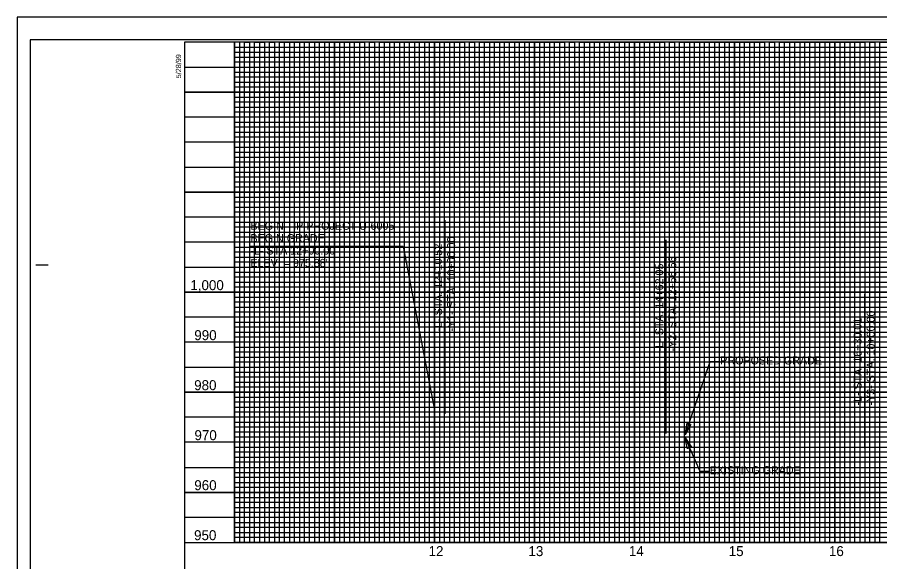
# Model space of a CAD drawing. Extents: x 1623313 to 1628771, y 891211 to 901910.
# Drawn here: x 1623313 to 1624175, y 901315 to 901859 of the extents above; entities that cross this region are included whole.
import ezdxf

# ---------------------------------------------------------------- set-up
doc = ezdxf.new("R2010")
doc.units = 0
for name, color, linetype in [('Default', 7, 'Continuous'), ('Prop DSN Text', 7, 'Continuous'), ('Prop VPI Label', 7, 'Continuous'), ('Scratch_Level_0', 7, 'Continuous'), ('Sheet Cutting Line CELL', 7, 'Continuous'), ('Sheet DOT Grid CELL', 7, 'Continuous'), ('Sheet Layout Profile Border Port 1', 7, 'Continuous'), ('Sheet Plot Border Inside CELL', 7, 'Continuous'), ('Sheet Plot Border Outside CELL', 7, 'Continuous'), ('Sheet Profile CELL', 7, 'Continuous'), ('Sheet Profile Grid Major CELL', 7, 'Continuous'), ('Sheet Profile Grid Middle CELL', 7, 'Continuous'), ('Sheet Profile Grid Minor CELL', 7, 'Continuous'), ('Typical Terminator CELL', 7, 'Continuous')]:
    doc.layers.add(name, color=color, linetype=linetype)

msp = doc.modelspace()

# ---------------------------------------------------------------- linework, layer by layer
at = {"layer": 'Prop DSN Text'}
for points in [[(1623740.48, 901480.56), (1623740.66, 901656.7)], [(1623961.49, 901443.17), (1623961.68, 901636.82)], [(1624160.08, 901428.57), (1624160.08, 901428.57), (1624160.15, 901582.49)], [(1623980.61, 901441.91), (1624005.61, 901515.32), (1624015.61, 901515.32)], [(1623740.47, 901463.06), (1623740.48, 901480.56)], [(1623980.04, 901439.52), (1623995.04, 901405.59), (1624005.04, 901405.59)]]:
    msp.add_lwpolyline(points, dxfattribs=at)
at = {"layer": 'Prop VPI Label'}
msp.add_line((1623698.63, 901630.21), (1623729.95, 901466.57), dxfattribs=at)
msp.add_lwpolyline([(1623698.63, 901630.21), (1623545.98, 901630.21), (1623698.63, 901630.21)], dxfattribs=at)
at = {"layer": 'Scratch_Level_0'}
msp.add_lwpolyline([(1623529.95, 901824.45), (1624929.95, 901824.45), (1624929.95, 901334.45), (1623529.95, 901334.45)], close=True, dxfattribs=at)
at = {"layer": 'Sheet Cutting Line CELL'}
for p, q in [((1624996.95, 901859.45), (1623312.95, 901859.45)), ((1623312.95, 901859.45), (1623312.95, 900759.45))]:
    msp.add_line(p, q, dxfattribs=at)
at = {"layer": 'Sheet DOT Grid CELL'}
for p, q in [((1623529.95, 901334.45), (1623529.95, 901834.45)), ((1623579.95, 901334.45), (1623579.95, 901834.45)), ((1623629.95, 901334.45), (1623629.95, 901834.45)), ((1623679.95, 901334.45), (1623679.95, 901834.45)), ((1623729.95, 901334.45), (1623729.95, 901834.45)), ((1623779.95, 901334.45), (1623779.95, 901834.45)), ((1623829.95, 901334.45), (1623829.95, 901834.45)), ((1623879.95, 901334.45), (1623879.95, 901834.45)), ((1623929.95, 901334.45), (1623929.95, 901834.45)), ((1623979.95, 901334.45), (1623979.95, 901834.45)), ((1624029.95, 901334.45), (1624029.95, 901834.45)), ((1624079.95, 901334.45), (1624079.95, 901834.45)), ((1624129.95, 901334.45), (1624129.95, 901834.45)), ((1624779.9, 901784.45), (1623479.95, 901784.45)), ((1624779.9, 901734.45), (1623479.95, 901734.45)), ((1624779.95, 901684.45), (1623479.95, 901684.45)), ((1624979.95, 901634.45), (1623479.95, 901634.45)), ((1624979.95, 901584.45), (1623479.95, 901584.45)), ((1624979.95, 901534.45), (1623479.95, 901534.45)), ((1624979.95, 901484.45), (1623479.95, 901484.45)), ((1624979.95, 901434.45), (1623479.95, 901434.45)), ((1624979.95, 901384.45), (1623479.95, 901384.45))]:
    msp.add_line(p, q, dxfattribs=at)
at = {"layer": 'Sheet Layout Profile Border Port 1'}
msp.add_lwpolyline([(1623529.95, 901673.4), (1623529.95, 901334.45), (1624929.95, 901334.45), (1624929.95, 901673.4)], dxfattribs=at)
at = {"layer": 'Sheet Plot Border Inside CELL'}
msp.add_lwpolyline([(1623325.95, 900781.9), (1624992.45, 900781.9), (1624992.45, 901837), (1623325.95, 901837)], close=True, dxfattribs=at)
at = {"layer": 'Sheet Plot Border Outside CELL'}
msp.add_lwpolyline([(1623312.95, 900759.45), (1624996.95, 900759.45), (1624996.95, 901859.45), (1623312.95, 901859.45)], close=True, dxfattribs=at)
at = {"layer": 'Sheet Profile CELL'}
for p, q in [((1623331.45, 901611.95), (1623343.95, 901611.95)), ((1623479.95, 901334.45), (1624979.95, 901334.45))]:
    msp.add_line(p, q, dxfattribs=at)
msp.add_lwpolyline([(1624979.95, 901834.45), (1623479.95, 901834.45), (1623479.95, 900784.45), (1624979.95, 900784.45)], close=True, dxfattribs=at)
at = {"layer": 'Sheet Profile Grid Major CELL'}
for points in [[(1623529.95, 901834.45), (1623529.95, 901334.45), (1623579.95, 901334.45), (1623579.95, 901834.45), (1623629.95, 901834.45), (1623629.95, 901334.45), (1623679.95, 901334.45), (1623679.95, 901834.45), (1623729.95, 901834.45), (1623729.95, 901334.45), (1623779.95, 901334.45), (1623779.95, 901834.45), (1623829.95, 901834.45), (1623829.95, 901334.45), (1623879.95, 901334.45), (1623879.95, 901834.45), (1623929.95, 901834.45), (1623929.95, 901334.45), (1623979.95, 901334.45), (1623979.95, 901834.45), (1624029.95, 901834.45), (1624029.95, 901334.45), (1624079.95, 901334.45), (1624079.95, 901834.45), (1624129.95, 901834.45), (1624129.95, 901334.45), (1624179.95, 901334.45)], [(1623479.95, 901784.45), (1624779.95, 901784.45)], [(1624779.95, 901734.45), (1623479.95, 901734.45), (1623479.95, 901684.45), (1624779.95, 901684.45)], [(1624979.95, 901634.45), (1623479.95, 901634.45), (1623479.95, 901584.45), (1624979.95, 901584.45)], [(1624979.95, 901534.45), (1623479.95, 901534.45), (1623479.95, 901484.45), (1624979.95, 901484.45)], [(1624979.95, 901434.45), (1623479.95, 901434.45), (1623479.95, 901434.45), (1623479.95, 901384.45), (1624979.95, 901384.45)]]:
    msp.add_lwpolyline(points, dxfattribs=at)
at = {"layer": 'Sheet Profile Grid Middle CELL'}
msp.add_line((1623479.95, 901809.45), (1624779.9, 901809.45), dxfattribs=at)
for points in [[(1623554.95, 901834.45), (1623554.95, 901334.45), (1623604.95, 901334.45), (1623604.95, 901834.45), (1623654.95, 901834.45), (1623654.95, 901334.45), (1623704.95, 901334.45), (1623704.95, 901834.45), (1623754.95, 901834.45), (1623754.95, 901334.45), (1623804.95, 901334.45), (1623804.95, 901834.45), (1623854.95, 901834.45), (1623854.95, 901334.45), (1623904.95, 901334.45), (1623904.95, 901834.45), (1623954.95, 901834.45), (1623954.95, 901334.45), (1624004.95, 901334.45), (1624004.95, 901834.45), (1624054.95, 901834.45), (1624054.95, 901334.45), (1624104.95, 901334.45), (1624104.95, 901334.45), (1624104.95, 901834.45), (1624154.95, 901834.45), (1624154.95, 901334.45), (1624204.95, 901334.45)], [(1624779.95, 901759.45), (1623479.95, 901759.45), (1623479.95, 901709.45), (1624779.95, 901709.45)], [(1624979.95, 901659.45), (1623479.95, 901659.45), (1623479.95, 901609.45), (1624804.95, 901609.45)], [(1624979.95, 901559.45), (1623479.95, 901559.45), (1623479.95, 901509.45), (1624979.95, 901509.45)], [(1624979.95, 901459.45), (1623479.95, 901459.45), (1623479.95, 901409.45), (1624979.95, 901409.45)], [(1624979.95, 901359.45), (1623479.95, 901359.45)]]:
    msp.add_lwpolyline(points, dxfattribs=at)
at = {"layer": 'Sheet Profile Grid Minor CELL'}
for p, q in [((1623529.95, 901829.45), (1624779.95, 901829.45)), ((1623529.95, 901824.45), (1623529.95, 901824.45)), ((1624779.95, 901824.45), (1623529.95, 901824.1)), ((1623529.95, 901819.45), (1624779.95, 901819.45)), ((1624779.9, 901699.45), (1623529.95, 901699.45)), ((1624779.95, 901694.45), (1623529.95, 901694.45)), ((1624779.95, 901689.45), (1623529.95, 901689.45)), ((1623529.95, 901679.45), (1624779.95, 901679.45)), ((1624779.95, 901674.45), (1623529.95, 901674.45)), ((1623529.95, 901669.45), (1624929.95, 901669.45)), ((1624929.95, 901649.45), (1623529.95, 901649.45)), ((1623529.95, 901644.45), (1624929.95, 901644.45)), ((1624929.95, 901624.45), (1623529.95, 901624.45)), ((1623529.95, 901619.45), (1624929.95, 901619.45)), ((1624929.95, 901599.45), (1623529.95, 901599.45)), ((1623529.95, 901594.45), (1624929.95, 901594.45)), ((1624929.95, 901589.45), (1623529.95, 901589.45)), ((1623529.95, 901579.45), (1624929.95, 901579.45)), ((1624929.95, 901574.45), (1623529.95, 901574.45)), ((1623529.95, 901569.45), (1624929.95, 901569.45)), ((1624929.95, 901564.45), (1623529.95, 901564.45)), ((1623529.95, 901554.45), (1624929.95, 901554.45)), ((1624929.95, 901549.45), (1623529.95, 901549.45)), ((1623529.95, 901544.45), (1624929.95, 901544.45)), ((1624929.95, 901539.45), (1623529.95, 901539.45)), ((1623529.95, 901529.45), (1624929.95, 901529.45)), ((1624929.95, 901524.45), (1623529.95, 901524.45)), ((1623529.95, 901519.45), (1624929.95, 901519.45)), ((1624929.95, 901514.45), (1623529.95, 901514.45)), ((1623529.95, 901504.45), (1624929.95, 901504.45)), ((1624929.95, 901499.45), (1623529.95, 901499.45)), ((1623529.95, 901494.45), (1624929.95, 901494.45)), ((1624929.95, 901489.45), (1623529.95, 901489.45)), ((1623529.95, 901479.45), (1624929.95, 901479.45)), ((1624929.95, 901474.45), (1623529.95, 901474.45)), ((1623529.95, 901469.45), (1624929.95, 901469.45)), ((1624929.95, 901464.45), (1623529.95, 901464.45)), ((1623529.95, 901454.45), (1624929.95, 901454.45)), ((1624929.95, 901449.45), (1623529.95, 901449.45)), ((1624929.95, 901444.45), (1623529.95, 901444.45)), ((1624929.95, 901439.45), (1623529.95, 901439.45)), ((1623529.95, 901429.45), (1624929.95, 901429.45)), ((1624929.95, 901424.45), (1623529.95, 901424.45)), ((1623529.95, 901419.45), (1624929.95, 901419.45)), ((1624929.95, 901414.45), (1623529.95, 901414.45)), ((1623529.95, 901404.45), (1624929.95, 901404.45)), ((1624929.95, 901399.45), (1623529.95, 901399.45)), ((1623529.95, 901394.45), (1624929.95, 901394.45)), ((1624929.95, 901389.45), (1623529.95, 901389.45)), ((1623529.95, 901379.45), (1624929.95, 901379.45)), ((1624929.95, 901374.45), (1623529.95, 901374.45)), ((1623529.95, 901369.45), (1624929.95, 901369.45)), ((1624929.95, 901364.45), (1623529.95, 901364.45)), ((1623529.95, 901354.45), (1624929.95, 901354.45)), ((1624929.95, 901349.45), (1623529.95, 901349.45)), ((1623529.95, 901344.45), (1624929.95, 901344.45))]:
    msp.add_line(p, q, dxfattribs=at)
for points in [[(1623534.95, 901834.45), (1623534.95, 901334.45), (1623539.95, 901334.45), (1623539.95, 901834.45), (1623544.95, 901834.45), (1623544.95, 901334.45), (1623549.95, 901334.45), (1623549.95, 901834.45), (1623559.95, 901834.45), (1623559.95, 901334.45), (1623564.95, 901334.45), (1623564.95, 901834.45), (1623569.95, 901834.45), (1623569.95, 901334.45), (1623574.95, 901334.45), (1623584.95, 901334.45), (1623589.95, 901334.45), (1623589.95, 901834.45), (1623594.95, 901834.45), (1623594.95, 901334.45), (1623599.95, 901334.45), (1623599.95, 901834.45), (1623609.95, 901834.45), (1623609.95, 901334.45), (1623614.95, 901334.45), (1623614.95, 901834.45), (1623619.95, 901834.45), (1623619.95, 901334.45), (1623624.95, 901334.45), (1623624.95, 901834.45), (1623634.95, 901834.45), (1623634.95, 901334.45), (1623639.95, 901334.45), (1623639.95, 901834.45), (1623644.95, 901834.45), (1623644.95, 901334.45), (1623649.95, 901334.45), (1623649.95, 901834.45), (1623659.95, 901834.45), (1623659.95, 901334.45), (1623664.95, 901334.45), (1623664.95, 901834.45), (1623669.95, 901834.45), (1623669.95, 901334.45), (1623674.95, 901334.45), (1623674.95, 901834.45), (1623684.95, 901834.45), (1623684.95, 901334.45), (1623689.95, 901334.45), (1623689.95, 901834.45), (1623694.95, 901834.45), (1623694.95, 901334.45), (1623699.95, 901334.45), (1623699.95, 901834.45), (1623709.95, 901834.45), (1623709.95, 901334.45), (1623714.95, 901334.45), (1623714.95, 901834.45), (1623719.95, 901834.45), (1623719.95, 901334.45), (1623724.95, 901334.45), (1623724.95, 901834.45), (1623734.95, 901834.45), (1623734.95, 901334.45), (1623739.95, 901334.45), (1623739.95, 901834.45), (1623744.95, 901834.45), (1623744.95, 901334.45)], [(1623574.95, 901334.45), (1623574.95, 901834.45), (1623584.95, 901834.45), (1623584.95, 901334.45)], [(1623744.95, 901334.45), (1623749.95, 901334.45), (1623749.95, 901834.45), (1623759.95, 901834.45), (1623759.95, 901334.45), (1623764.95, 901334.45), (1623764.95, 901834.45), (1623769.95, 901834.45), (1623769.95, 901334.45), (1623774.95, 901334.45), (1623774.95, 901834.45), (1623784.95, 901834.45), (1623784.95, 901334.45), (1623789.95, 901334.45), (1623789.95, 901834.45), (1623794.95, 901834.45), (1623794.95, 901334.45), (1623799.95, 901334.45), (1623799.95, 901834.45), (1623809.95, 901834.45), (1623809.95, 901334.45), (1623814.95, 901334.45), (1623814.95, 901834.45), (1623819.95, 901834.45), (1623819.95, 901334.45), (1623824.95, 901334.45), (1623824.95, 901834.45), (1623834.95, 901834.45), (1623834.95, 901334.45), (1623839.95, 901334.45), (1623839.95, 901834.45), (1623844.95, 901834.45), (1623844.95, 901334.45), (1623849.95, 901334.45), (1623849.95, 901834.45), (1623859.95, 901834.45), (1623859.95, 901334.45), (1623864.95, 901334.45), (1623864.95, 901834.45), (1623869.95, 901834.45), (1623869.95, 901334.45), (1623874.95, 901334.45), (1623874.95, 901834.45), (1623884.95, 901834.45), (1623884.95, 901334.45), (1623889.95, 901334.45), (1623889.95, 901834.45), (1623894.95, 901834.45), (1623894.95, 901334.45), (1623899.95, 901334.45), (1623899.95, 901834.45), (1623909.95, 901834.45), (1623909.95, 901334.45), (1623914.95, 901334.45), (1623914.95, 901834.45), (1623919.95, 901834.45), (1623919.95, 901334.45), (1623924.95, 901334.45), (1623924.95, 901834.45), (1623934.95, 901834.45), (1623934.95, 901334.45), (1623939.95, 901334.45), (1623939.95, 901834.45), (1623944.95, 901834.45), (1623944.95, 901334.45), (1623949.95, 901334.45), (1623949.95, 901834.45), (1623959.95, 901834.45), (1623959.95, 901334.45), (1623964.95, 901334.45), (1623964.95, 901834.45), (1623969.95, 901834.45), (1623969.95, 901334.45), (1623974.95, 901334.45), (1623974.95, 901834.45), (1623984.95, 901834.45), (1623984.95, 901334.45), (1623989.95, 901334.45), (1623989.95, 901834.45), (1623994.95, 901834.45), (1623994.95, 901334.45), (1623999.95, 901334.45), (1623999.95, 901834.45), (1624009.95, 901834.45), (1624009.95, 901334.45), (1624014.95, 901334.45), (1624014.95, 901834.45), (1624019.95, 901834.45), (1624019.95, 901334.45), (1624024.95, 901334.45), (1624024.95, 901834.45), (1624034.95, 901834.45), (1624034.95, 901334.45), (1624039.95, 901334.45), (1624039.95, 901834.45), (1624044.95, 901834.45), (1624044.95, 901334.45), (1624049.95, 901334.45), (1624049.95, 901834.45), (1624059.95, 901834.45)], [(1624059.95, 901834.45), (1624059.95, 901334.45), (1624064.95, 901334.45), (1624064.95, 901834.45), (1624069.95, 901834.45), (1624069.95, 901334.45), (1624074.95, 901334.45), (1624074.95, 901834.45), (1624084.95, 901834.45), (1624084.95, 901334.45), (1624089.95, 901334.45), (1624089.95, 901834.45), (1624094.95, 901834.45), (1624094.95, 901334.45), (1624099.95, 901334.45), (1624099.95, 901834.45), (1624109.95, 901834.45), (1624109.95, 901334.45), (1624114.95, 901334.45), (1624114.95, 901834.45), (1624119.95, 901834.45), (1624119.95, 901334.45), (1624124.95, 901334.45), (1624124.95, 901834.45), (1624134.95, 901834.45), (1624134.95, 901334.45), (1624139.95, 901334.45), (1624139.95, 901834.45), (1624144.95, 901834.45), (1624144.95, 901334.45), (1624149.95, 901334.45), (1624149.95, 901834.45), (1624159.95, 901834.45), (1624159.95, 901334.45), (1624164.95, 901334.45), (1624164.95, 901834.45), (1624169.95, 901834.45), (1624169.95, 901334.45), (1624174.95, 901334.45), (1624174.95, 901834.45), (1624184.95, 901834.45)], [(1624779.95, 901814.45), (1623529.95, 901814.45), (1623529.95, 901804.45), (1624779.95, 901804.45)], [(1624779.9, 901799.45), (1623529.95, 901799.45), (1623529.95, 901794.45), (1624779.95, 901794.45)], [(1624779.95, 901789.45), (1623529.95, 901789.45), (1623529.95, 901779.45), (1624779.95, 901779.45)], [(1624779.95, 901774.45), (1623529.95, 901774.45), (1623529.95, 901769.45), (1624779.95, 901769.45)], [(1624779.95, 901764.45), (1623529.95, 901764.45), (1623529.95, 901754.45), (1624779.95, 901754.45)], [(1624779.95, 901749.45), (1623529.95, 901749.45), (1623529.95, 901744.45), (1624779.95, 901744.45)], [(1624779.95, 901739.45), (1623529.95, 901739.45), (1623529.95, 901729.45), (1624779.95, 901729.45)], [(1624779.95, 901724.35), (1623530.05, 901724.35), (1623530.05, 901719.45), (1624779.95, 901719.45)], [(1624779.95, 901714.45), (1623529.95, 901714.45), (1623529.95, 901704.45), (1624779.95, 901704.45)], [(1624929.95, 901664.45), (1623529.95, 901664.45), (1623529.95, 901654.45), (1624929.95, 901654.45)], [(1624929.95, 901639.45), (1623529.95, 901639.45), (1623529.95, 901629.45), (1624929.95, 901629.45)], [(1624929.95, 901614.45), (1623529.95, 901614.45), (1623529.95, 901604.45), (1624929.95, 901604.45)], [(1624929.95, 901339.45), (1623529.95, 901339.45)]]:
    msp.add_lwpolyline(points, dxfattribs=at)
at = {"layer": 'Typical Terminator CELL'}
for points in [[(1623986.3, 901452.35), (1623980.61, 901441.91), (1623982.44, 901453.73), (1623983.93, 901451.64)], [(1623982.93, 901427.98), (1623980.04, 901439.52), (1623986.71, 901429.58), (1623984.2, 901430.11)]]:
    msp.add_lwpolyline(points, close=True, dxfattribs=at)

# ---------------------------------------------------------------- texts
at = {"layer": 'Default'}
for s, p in [('1,000', (1623485.93, 901586.61)), ('990', (1623489.89, 901536.61)), ('980', (1623489.78, 901486.61)), ('970', (1623490.05, 901436.61)), ('960', (1623489.89, 901386.61)), ('950', (1623489.67, 901336.61)), ('12', (1623724.05, 901320.7)), ('13', (1623823.89, 901320.7)), ('14', (1623924.27, 901320.7)), ('15', (1624024.05, 901320.7)), ('16', (1624124.19, 901320.7))]:
    msp.add_text(s, height=10, dxfattribs=at).set_placement(p)
at = {"layer": 'Prop DSN Text'}
for s, p in [('-Y1- STA. 10+00.00', (1623750.6, 901545.32)), ('-L- STA. 12+10.52', (1623737.6, 901545.32)), ('-Y2- STA. 12+56.66', (1623971.62, 901525.43)), ('-L- STA. 14+62.05', (1623958.62, 901525.43)), ('-Y3- STA. 10+00.00', (1624169.91, 901471.31)), ('-L- STA. 16+30.01', (1624156.91, 901471.31))]:
    msp.add_text(s, height=8, rotation=90, dxfattribs=at).set_placement(p)
for s, p in [('PROPOSED GRADE', (1624015.61, 901512.32)), ('EXISTING GRADE', (1624005.04, 901402.59))]:
    msp.add_text(s, height=8, dxfattribs=at).set_placement(p)
at = {"layer": 'Prop VPI Label'}
for s, p in [('BEGIN TIP PROJECT U-6005', (1623545.98, 901646.96)), ('BEGIN GRADE', (1623545.98, 901634.59)), ('-L- STA 12+00.00', (1623545.98, 901622.21)), ("ELEV. = 975.88'", (1623545.98, 901609.84))]:
    msp.add_text(s, height=8, dxfattribs=at).set_placement(p)
at = {"layer": 'Sheet Profile CELL'}
msp.add_text('5/28/99', height=5.25, rotation=90, dxfattribs=at).set_placement((1623476.71, 901798.36))

doc.saveas('drawing.dxf')
